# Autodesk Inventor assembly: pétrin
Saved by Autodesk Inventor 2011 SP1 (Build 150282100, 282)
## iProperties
Created: 2010-12
Part Number: pétrin
Document SubType Name: Assembly
Designer: eric
Author: eric
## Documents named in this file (7)
- D:\eduinventor\maquettesaip2011\machineàpain\Workspace\pétrin.iam
- D:\eduinventor\maquettesaip2011\machineàpain\Workspace\accouplement axe de petrin.ipt
- D:\eduinventor\maquettesaip2011\machineàpain\Workspace\axe de petrin.ipt
- D:\eduinventor\maquettesaip2011\machineàpain\Workspace\coussinet 8 12x12.ipt
- D:\eduinventor\maquettesaip2011\machineàpain\Workspace\pétrin.ipt
- D:\eduinventor\maquettesaip2011\machineàpain\Workspace\Anneau élastique pour arbre, 8x0.8.ipt
- D:\eduinventor\maquettesaip2011\machineàpain\Workspace\rondelle de frottement axe de petrin.ipt
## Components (8 placed, 6 different names)
1. accouplement axe de petrin:1
2. axe de petrin:1
3. coussinet 8 12x12:1
4. pétrin:1
5. Anneau élastique pour arbre, 8x0.8:1
6. Anneau élastique pour arbre, 8x0.8:2
7. rondelle de frottement axe de petrin:1
8. rondelle de frottement axe de petrin:2
